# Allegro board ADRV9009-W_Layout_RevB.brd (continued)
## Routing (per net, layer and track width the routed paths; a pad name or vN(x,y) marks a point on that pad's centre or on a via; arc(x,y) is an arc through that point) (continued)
ORX2_UNBAL: length 2.3
  BOTTOM w0.203: C251.1 18.65,18
  BOTTOM w0.394: R223.2 17.76,17.01 C224.1 18.65,18
OUT1: length 3.9
  BOTTOM w0.203: 96.65,60.56 96.97,60.56 97.16,60.56 97.47,60.87 R420.1 ; 96.65,60.56 96.63,60.58 R418.1 ; 96.65,60.56 95.11,60.56 95.04,60.63 U401.64
OUT1_N: length 4
  BOTTOM w0.203: 96.65,60.2 96.63,60.18 R418.2 ; 96.65,60.2 95.11,60.2 95.04,60.13 U401.65 ; 96.65,60.2 97.13,60.2 97.47,59.86 R419.1
OUT3: length 3.9
  BOTTOM w0.203: 96.72,63.56 97.57,63.56 R424.1 ; 96.72,63.56 95.16,63.56 95.09,63.63 94.47,63.63 U401.58 ; 96.72,63.56 R423.2
OUT3_N: length 3.9
  BOTTOM w0.203: R425.1 97.57,63.2 96.72,63.2 ; 96.72,63.2 95.16,63.2 95.09,63.13 U401.59 ; 96.72,63.2 R423.1
OUT5: length 19.1
  TOP w0.203: C410.1 105.16,64.38 105.42,64.65 105.42,64.89 105.22,65.09 103.66,65.09 103.25,64.68 95.25,64.68 94.21,65.72 91.52,65.72 91.11,66.14 91.11,66.66 91,66.78 ; 91,66.78 R426.1 ; 91,66.78 90.93,66.84 v2(90.93,67.34)
  BOTTOM w0.203: U401.49 91.04,66.29 91.11,66.36 91.11,67.17 v2(90.93,67.34)
OUT5_N: length 19.1
  TOP w0.203: C411.1 106.05,64.38 105.78,64.65 105.78,65.03 105.37,65.44 103.51,65.44 103.11,65.04 95.4,65.04 94.36,66.08 91.67,66.08 91.47,66.28 91.47,66.66 91.63,66.83 ; 91.63,66.83 91.65,66.84 v2(91.65,67.34) ; 91.63,66.83 91.63,66.82 R426.2
  BOTTOM w0.203: U401.50 91.54,66.26 91.47,66.33 91.47,67.17 v2(91.65,67.34)
OUT7: length 13.9
  TOP w0.203: 87.95,66.83 88.11,66.66 88.11,66.28 87.91,66.08 85.92,66.08 85.35,66.65 80.13,66.65 79.82,66.97 78.91,66.97 78.5,66.56 78.5,66.21 C412.1 ; 87.95,66.83 87.93,66.84 v2(87.93,67.34) ; 87.95,66.83 R427.1
  BOTTOM w0.203: v2(87.93,67.34) 88.11,67.17 88.11,66.33 88.04,66.26 U401.43
OUT7_N: length 13.8
  TOP w0.203: 88.58,66.78 88.65,66.84 v2(88.65,67.34) ; 88.58,66.78 88.47,66.66 88.47,66.14 88.06,65.72 85.77,65.72 85.2,66.3 79.99,66.3 79.67,66.61 79.06,66.61 78.86,66.41 78.86,66.21 C413.1 ; 88.58,66.78 R427.2
  BOTTOM w0.203: U401.44 88.54,66.29 88.47,66.36 88.47,67.17 v2(88.65,67.34)
OUT8: length 22.7
  TOP w0.203: 85.73,67.76 R428.1 ; 85.73,67.76 70.86,67.76 70.58,67.48 70.18,67.48 69.9,67.76 69.49,67.76 68.75,67.01 68.75,66.61 68.87,66.49 69.45,66.49 69.59,66.35 69.59,66.06 R429.1 ; 85.73,67.76 86.57,67.76 86.79,67.53 86.79,67.16 86.66,67.04 86.66,66.95 86.55,66.84 v2(86.43,66.84)
  BOTTOM w0.203: v2(86.43,66.84) 86.61,66.66 86.61,66.33 86.54,66.26 U401.40
OUT8_N: length 22.7
  TOP w0.203: v2(87.15,66.84) 87.15,67.68 86.71,68.11 85.73,68.11 ; 85.73,68.11 69.34,68.11 68.39,67.16 R430.1 ; 85.73,68.11 R428.2
  BOTTOM w0.203: v2(87.15,66.84) 86.97,66.66 86.97,66.36 87.04,66.29 U401.41
OUT12: length 7.1
  BOTTOM w0.203: R431.2 80.57,63.56 ; 80.57,63.56 82.03,63.56 82.26,63.33 82.26,61.65 82.7,61.2 83.47,61.2 83.54,61.13 U401.28 ; 80.57,63.56 80.01,63.56 79.77,63.32 R432.1
OUT12_N: length 7.2
  BOTTOM w0.203: R433.1 79.76,64.21 80.05,63.92 80.58,63.92 ; 80.58,63.92 82.17,63.92 82.62,63.48 82.62,61.79 82.85,61.56 83.47,61.56 83.54,61.63 U401.29 ; 80.58,63.92 80.57,63.93 R431.1
OUT13: length 3.9
  BOTTOM w0.203: 81.75,59.71 81.06,59.71 R436.1 ; 81.75,59.71 R434.1 ; 81.75,59.71 83.63,59.71 83.72,59.63 U401.25
OUT13_N: length 3.9
  BOTTOM w0.203: R434.2 81.75,60.07 ; 81.75,60.07 83.62,60.07 83.68,60.13 U401.26 ; 81.75,60.07 81.06,60.07 R435.1
PWRSUPPLYENABLE: length 111.8
  TOP w0.305: R902.1 79.66,19.07 v2(79.68,19.06)
  L8_SIG w0.394: v1(140.3,60.87) 142.31,60.87 143.58,59.6 143.58,49.9 145.04,48.45 145.04,33.69 143.58,32.24 143.58,22.2 143.19,21.81 142.66,21.81 142.31,21.46 142.31,20.87 141.98,20.54 141.39,20.54 138.89,18.04 127.56,18.04 127.02,18.58 123.59,18.58 122.42,19.75 121.66,19.75 121.39,19.48 120.1,19.48 120.09,19.47 119.55,19.47 119.54,19.48 116.34,19.48 115.71,20.11 98.31,20.11 97.31,19.11 79.73,19.11 v2(79.68,19.06)
  BOTTOM w0.394: v1(140.3,60.87) 139.74,60.31 P801.D1
REF_CLK_IN+: length 62.9
  BOTTOM w0.203: 78.74,59.71 79.47,59.71 R436.2 ; 78.74,59.71 77.41,59.71 ; 78.74,59.71 C445.2 ; 77.41,59.71 L401.1 ; 77.41,59.71 77.09,59.71 arc(72.18,59.25) 67.44,57.88 arc(67.04,57.73) 66.63,57.6 66.64,57.6 arc(58.87,55.89) 50.94,55.27 50.94,55.27 arc(47.52,53.86) 46.11,50.44 46.11,45.64 arc(44.94,42.82) 42.12,41.65 38.29,41.65 arc(35.41,41.03) 33.1,39.2 arc(32.44,38) 32.21,36.64 32.21,35.86 ; 32.21,35.86 32.21,35.59 arc(32.24,35.42) C103.1 ; 32.21,35.86 R121.1
REF_CLK_IN-: length 63.5
  BOTTOM w0.203: R121.2 31.85,35.86 ; 31.85,35.86 31.85,35.59 arc(31.81,35.42) C104.1 ; 31.85,35.86 31.85,36.64 arc(32.1,38.12) 32.83,39.43 arc(35.26,41.35) 38.29,42 42.12,42 arc(44.69,43.07) 45.75,45.64 45.75,50.44 arc(47.27,54.11) 50.94,55.62 arc(58.82,56.24) 66.54,57.94 arc(66.93,58.06) 67.31,58.21 arc(72.11,59.6) 77.09,60.07 77.41,60.07 ; 77.41,60.07 L401.2 ; 77.41,60.07 78.74,60.07 ; 78.74,60.07 79.47,60.07 R435.2 ; 78.74,60.07 C445.1
RESETB: length 120
  TOP w0.254: U101.J4 v3(35.64,31.68)
  TOP w0.394: R804.1 129.42,48.5 128.99,48.07 TP803.1
  L5_SIG w0.114: v3(35.64,31.68) 36.08,31.23 38.14,31.23 38.44,31.53 38.44,31.81 38.74,32.11 39,32.11 39.22,32.34 39.22,33.91 39.23,33.92 39.23,34.74 38.44,35.52 38.44,39.08 38.65,39.28 39.89,39.28 40.83,40.22 v5(40.9,40.22) 48.34,40.22 51.1,37.46 68.6,37.46 72.43,41.29 72.43,41.85 73.08,42.5 73.51,42.5 74.93,43.92 76.2,43.92 78.35,46.07 88.39,46.07 88.74,46.43 101.89,46.43 107.63,52.17 113.92,52.17 114.81,51.28 120.46,51.28 123.68,48.07 TP803.1
  BOTTOM w0.305: v5(40.9,40.22) 40.9,39.35 40.16,38.61 R110.2
RF_EXT_LO+: length 5.8
  TOP w0.203: U101.B8 v3(29.24,34.88)
  L10_SIG w0.254: v5(25.19,34.37) 25.47,34.09 27.83,34.09 27.98,34.24 28.89,34.24 29.24,34.58 v3(29.24,34.88)
  BOTTOM w0.203: C304.2 v5(25.19,34.37)
RF_EXT_LO-: length 5.8
  TOP w0.203: U101.B7 v3(29.24,33.28)
  L10_SIG w0.254: v5(25.19,33.45) 25.47,33.73 27.97,33.73 28.13,33.89 28.96,33.89 29.24,33.61 v3(29.24,33.28)
  BOTTOM w0.203: C305.2 v5(25.19,33.45)
RF_SYNTH_VTUNE: length 29.9
  TOP w0.203: C136.1 56.46,41.45 P104.5
  TOP w0.254: v5(34.04,35.68) U101.G9
  L7_SIG w0.114: v5(34.04,35.68) 34.42,36.06 34.42,38.13 34.83,38.54 34.98,38.54 35.18,38.74 35.18,38.9 35.56,39.28 42.99,39.28 44.9,41.19 46.99,41.19 48.33,42.52 51.95,42.52 52.13,42.34 53.24,42.34 53.48,42.58 55.18,42.58 P104.5
RFO_1: length 1
  TOP w0.203: 35.49,51.45 35.5,51.8 ; 35.5,52.39 C337.1
  TOP w0.394: 35.5,51.8 35.5,52.39
RFO_2: length 1
  TOP w0.203: 34.18,16.7 34.18,16.35 ; 34.17,15.77 C336.1
  TOP w0.394: 34.18,16.35 34.17,15.77
RX1_BAL+: length 3.3
  TOP w0.127: 18.86,38.89 T201.5
  TOP w0.203: 20.46,39.24 19.85,39.24 arc(19.32,39.15) 18.86,38.89 arc(18.8,38.84) T201.5 ; 20.46,39.24 C204.1 ; 20.46,39.24 20.84,39.24 arc(21.2,39.17) R205.1
RX1_BAL-: length 3.1
  TOP w0.203: 20.46,39.6 19.84,39.6 arc(19.25,39.71) T201.4 ; 20.46,39.6 C204.2 ; 20.46,39.6 20.84,39.6 arc(21.2,39.67) R206.1
RX1_ENABLE: length 37
  TOP w0.254: U101.M5 v3(38.04,31.68)
  TOP w0.305: P104.7 53.91,41.44 R117.1
  L5_SIG w0.114: v3(38.04,31.68) 37.67,32.04 37.15,32.04 36.77,32.42 36.77,32.62 36.58,32.81 36.38,32.81 36.06,33.14 36.06,33.46 35.3,34.21 35.3,41.05 38.35,44.1 39.49,44.1 40.25,44.86 49.86,44.86 53.34,41.38 P104.7
  BOTTOM w0.203: R839.1 P104.7
RX1_IN+: length 8.4
  TOP w0.203: U101.A9 28.7,35.41 arc(28.58,35.49) 28.44,35.52 arc(27.72,35.68) 27.12,36.11 25.16,38.34 arc(24.28,39) 23.21,39.24 ; 23.21,39.24 23.2,39.24 C207.1 ; 23.21,39.24 arc(23.12,39.24) 23.02,39.24 arc(22.56,39.17) R205.2
RX1_IN-: length 8.4
  TOP w0.203: 23.22,39.6 23.2,39.6 C207.2 ; 23.22,39.6 arc(24.43,39.32) 25.42,38.58 27.39,36.35 arc(27.86,36) 28.44,35.88 28.5,35.88 arc(28.63,35.9) 28.74,35.98 U101.A10 ; 23.22,39.6 arc(23.11,39.6) 23.01,39.6 arc(22.55,39.66) R206.2
RX1_UNBAL: length 2.2
  TOP w0.203: C248.1 13.11,40.1
  TOP w0.394: R202.2 C203.1 12.51,40.61 arc(12.65,40.48) 12.79,40.34 arc(12.95,40.22) 13.11,40.1
RX2_BAL+: length 3.6
  TOP w0.127: T202.5 19.12,29.57
  TOP w0.203: 20.46,29.75 20.84,29.75 arc(21.2,29.67) R212.1 ; 20.46,29.75 19.85,29.75 arc(19.47,29.7) 19.12,29.57 arc(18.92,29.44) T202.5 ; 20.46,29.75 C211.1
RX2_BAL-: length 3.1
  TOP w0.203: 20.46,30.1 19.84,30.1 arc(19.25,30.22) T202.4 ; 20.46,30.1 C211.2 ; 20.46,30.1 20.84,30.1 arc(21.2,30.17) R213.1
RX2_ENABLE: length 31.3
  TOP w0.254: U101.M7 v3(38.04,34.08)
  TOP w0.305: P104.8 53.91,38.77 R116.1
  L5_SIG w0.114: v3(38.04,34.08) 37.66,34.46 37.66,35 37.37,35.29 37.08,35.29 36.84,35.53 36.84,40.69 38.6,42.45 43.05,42.45 43.44,42.85 48.19,42.85 50.93,40.11 52.58,40.11 P104.8
  BOTTOM w0.203: R842.1 P104.8
RX2_IN+: length 7.6
  TOP w0.203: 23.21,29.74 23.02,29.75 arc(22.56,29.69) R212.2 ; 23.21,29.74 C214.1 ; 23.21,29.74 arc(23.98,29.85) 24.7,30.16 arc(25.8,30.85) 26.84,31.61 arc(27.61,32.06) 28.47,32.28 arc(28.69,32.23) U101.A5
RX2_IN-: length 7.7
  TOP w0.203: U101.A6 28.7,32.74 arc(28.58,32.66) 28.44,32.63 arc(27.47,32.39) 26.62,31.89 arc(25.59,31.14) 24.52,30.47 arc(23.88,30.19) 23.19,30.1 ; 23.19,30.1 23.02,30.1 arc(22.56,30.17) R213.2 ; 23.19,30.1 arc(23.2,30.17) C214.2
RX2_UNBAL: length 4.1
  TOP w0.203: C249.1 12.96,30.56
  TOP w0.394: 12.96,30.56 11.88,30.56 arc(11.1,30.23) 10.78,29.45 C210.1 R209.2
SERDIN0+: length 3
  BOTTOM w0.203: P801.A22 143.55,33.02 arc(143.61,32.88) 143.75,32.82 145.7,32.82 arc(145.87,32.85) 146.02,32.95 C113.1
SERDIN0-: length 3
  BOTTOM w0.203: C114.1 146.02,32.33 arc(145.87,32.43) 145.7,32.46 143.75,32.46 arc(143.61,32.4) 143.55,32.26 P801.A23
SERDIN1+: length 3
  BOTTOM w0.203: C115.1 146.02,22.79 arc(145.87,22.69) 145.7,22.66 143.75,22.66 arc(143.61,22.72) 143.55,22.86 P801.A30
SERDIN1-: length 3
  BOTTOM w0.203: C116.1 146.02,22.17 arc(145.87,22.27) 145.7,22.3 143.75,22.3 arc(143.61,22.24) 143.55,22.1 P801.A31
SERDIN2+: length 1.4
  TOP w0.203: v1(141.64,58.04) C117.1
  BOTTOM w0.203: P801.C2 v1(141.64,58.04)
SERDIN2-: length 1.7
  TOP w0.203: v1(141.64,56.77) C118.1
  BOTTOM w0.203: 141.19,57.22 v1(141.64,56.77) ; 141.19,57.22 P801.C3 141.03,57.4 141.19,57.24 141.19,57.22
SERDIN3+: length 3
  BOTTOM w0.203: P801.A26 143.55,27.94 arc(143.61,27.8) 143.75,27.74 145.7,27.74 arc(145.87,27.77) 146.02,27.87 C119.1
SERDIN3-: length 3
  BOTTOM w0.203: C120.1 146.02,27.25 arc(145.87,27.35) 145.7,27.38 143.75,27.38 arc(143.61,27.32) 143.55,27.18 P801.A27
SERDOUT0+: length 3
  BOTTOM w0.203: P801.A2 143.55,58.42 arc(143.61,58.28) 143.75,58.22 145.7,58.22 arc(145.87,58.25) 146.02,58.35 C105.1
SERDOUT0-: length 3
  BOTTOM w0.203: C106.1 146.02,57.73 arc(145.87,57.83) 145.7,57.86 143.75,57.86 arc(143.61,57.8) 143.55,57.66 P801.A3
SERDOUT1+: length 3
  BOTTOM w0.203: C107.1 146.02,53.27 arc(145.87,53.17) 145.7,53.14 143.75,53.14 arc(143.61,53.2) 143.55,53.34 P801.A6
SERDOUT1-: length 3
  BOTTOM w0.203: C108.1 146.02,52.65 arc(145.87,52.75) 145.7,52.78 143.75,52.78 arc(143.61,52.72) 143.55,52.58 P801.A7
SERDOUT2+: length 1.4
  TOP w0.203: C109.1 141.67,52.93 v1(141.67,52.95)
  BOTTOM w0.203: v1(141.67,52.95) 141.66,52.95 P801.C6
SERDOUT2-: length 1.4
  TOP w0.203: v1(141.64,51.69) C110.1
  BOTTOM w0.203: v1(141.64,51.69) P801.C7
SERDOUT3+: length 3
  BOTTOM w0.203: C111.1 146.02,48.19 arc(145.87,48.09) 145.7,48.06 143.75,48.06 arc(143.61,48.12) 143.55,48.26 P801.A10
SERDOUT3-: length 3
  BOTTOM w0.203: C112.1 146.02,47.57 arc(145.87,47.67) 145.7,47.7 143.75,47.7 arc(143.61,47.64) 143.55,47.5 P801.A11
SPI_CLK: length 112.9
  TOP w0.254: U101.K9 v3(36.44,35.68) ; U403.3 120.14,47.94 121.68,46.4 121.68,44.26 TP805.1
  TOP w0.305: TP805.1 121.6,41.95 129.64,41.95 131.17,43.47 R806.1
  L7_SIG w0.114: TP805.1 119.37,41.95 105.16,41.95 100.9,46.2 89.79,46.2 v4(89.47,45.89)
  L8_SIG w0.114: v4(89.47,45.89) 89.29,46.07 77.72,46.07 77.09,45.44 72.39,45.44 70.36,43.41 51.69,43.41 45.21,36.93 43.18,36.93 41.54,35.29 37.08,35.29 36.69,35.68 v3(36.44,35.68)
SPI_CLK_9528: length 43.5
  TOP w0.203: U403.12 v2(120.14,53.63)
  L7_SIG w0.114: v2(120.14,53.63) 98.81,53.63 98.43,54.01 87.82,54.01 83.76,58.08 82.42,58.08 v2(82.21,58.29)
  BOTTOM w0.254: v2(82.21,58.29) 82.46,58.04 83.38,58.04 83.47,58.13 U401.22
SPI_CS0: length 119.8
  TOP w0.254: v1(139.1,42.87) 138.89,42.87 138.55,42.53 R832.2 R846.1 ; U402.7 116.71,47.86 117.33,47.24 118.65,47.24 119.9,45.99 TP816.1 ; U101.K10 v3(36.44,36.48)
  L7_SIG w0.114: TP816.1 119.34,44.84 116.88,44.84 115,42.97 105.67,42.97 101.6,47.03 96.52,47.03 96.01,47.54 v4(88.2,47.54)
  L8_SIG w0.114: v4(88.2,47.54) 72.08,47.54 68.84,44.3 48.96,44.3 44.88,40.22 43.42,40.22 40.43,37.22 40.36,37.22 40.01,36.88 36.84,36.88 v3(36.44,36.48)
  L8_SIG w0.254: TP816.1 121.98,44.49 123.63,44.49 124.64,43.48 138.49,43.48 v1(139.1,42.87)
SPI_CS1: length 34.8
  TOP w0.254: 121.44,50.48 U403.5
  TOP w0.305: U402.1 120.6,51.32 121.44,50.48 122.03,51.08 123.99,51.08 TP815.1 130.59,49.7 130.74,49.86 134.53,49.86 135.89,48.49 135.89,47.6 136.27,47.22 136.74,47.22 137.12,46.84 137.12,40.05 137.5,39.67 138.21,39.67 138.55,40.01 R833.2 R847.1
SPI_CS_9528: length 46.6
  TOP w0.203: U403.10 v2(121.44,53.63)
  L7_SIG w0.114: v2(81.7,57.55) 83.33,57.55 87.31,53.58 87.4,53.58 87.6,53.38 98.05,53.38 98.68,52.74 103.63,52.74 104.14,52.24 105.03,52.24 105.54,52.74 114.81,52.74 115.06,53 120.8,53 v2(121.44,53.63)
  BOTTOM w0.254: U401.21 83.78,57.63 83.69,57.63 83.62,57.55 v2(81.7,57.55)
SPI_DIN: length 114.2
  TOP w0.254: U403.4 120.79,48.18 123,45.96 TP806.1 ; U101.J9 v3(35.64,35.68)
  TOP w0.305: TP806.1 125.39,43.98 129.45,43.98 130.14,44.67 R807.1
  L7_SIG w0.114: TP806.1 122.03,47.33 117.4,47.33 113.93,43.86 106.18,43.86 102.24,47.8 96.97,47.8 96.58,48.19 85.49,48.19 v3(84.01,46.71)
  L8_SIG w0.114: v3(35.64,35.68) 36.03,36.06 40.43,36.06 40.85,36.48 41.33,36.48 43.06,38.2 44.33,38.2 49.98,43.85 69.6,43.85 72.45,46.7 84,46.7 v3(84.01,46.71)
SPI_DIN_9528: length 42.5
  TOP w0.203: U403.11 v2(120.79,56.55)
  L7_SIG w0.114: v2(120.79,56.55) 119.01,54.78 109.35,54.78 109.1,55.03 94.62,55.03 93.72,55.93 87.88,55.93 85.09,58.71 83.36,58.71 v2(83.28,58.63)
  BOTTOM w0.254: v2(83.28,58.63) 83.68,58.63 U401.23
SPI_DOUT: length 31.1
  TOP w0.203: 116.2,48.63 U402.6 ; 117.59,45.99 TP811.1
  TOP w0.254: U402.3 116.21,48.65 116.19,48.62 116.19,47.39 118.66,44.92 118.66,42.26 119.6,41.31 132.84,41.31 133.69,42.16 134.13,42.16 134.53,42.56 134.53,42.81 135.26,43.54 135.51,43.54 136.06,44.09 136.06,45.94 R845.1
SPI_DOUT_9528: length 38.8
  TOP w0.203: R453.2 114.11,55.92 TP400.1
  L7_SIG w0.114: TP400.1 96.78,55.92 93.73,58.97 86.49,58.97 86.06,59.4 83.01,59.4 v2(82.56,58.95)
  BOTTOM w0.254: v2(82.56,58.95) 82.83,59.21 83.59,59.21 83.67,59.13 83.81,59.13 U401.24
SPI_DOUT_DUT: length 91.5
  TOP w0.254: R454.2 116.07,44.56 TP401.1 ; U101.J10 v3(35.64,36.48)
  L7_SIG w0.097: 39.49,33.69 39.89,33.69
  L7_SIG w0.114: 39.49,33.69 37.95,33.69 37.63,34.01 37.63,34.24 37.4,34.46 37.1,34.46 36.07,35.5 36.07,36.04 v3(35.64,36.48) ; v2(79.64,37.38) 78.43,37.38 77.03,35.98 77.03,35.84 74.6,33.41 45.85,33.41 45.3,33.96 44.71,33.96 44.45,34.22 43.2,34.22 42.67,33.69 39.89,33.69
  BOTTOM w0.394: v2(79.64,37.38) 111.83,37.38 TP401.1
STATUS_0: length 3.2
  TOP w0.203: R444.1 v2(95.57,65.95)
  BOTTOM w0.254: R444.1 95.57,66.59 ; v2(95.57,65.95) 94.75,65.13 U401.55
  BOTTOM w0.394: 95.57,66.59 v2(95.57,65.95)
STATUS_1: length 4.5
  TOP w0.203: v2(96.64,65.95) 96.64,66.69 R445.1
  BOTTOM w0.254: v2(96.64,65.95) 96.52,65.95 95.2,64.63 U401.56
  BOTTOM w0.394: v2(96.64,65.95) R443.1
SYNCINB0+: length 148.6
  TOP w0.203: R820.1 137.81,49.13 v1(137.83,49.15)
  TOP w0.254: U101.M4 v3(38.04,30.88)
  L7_SIG w0.091: v3(38.04,30.88) 38.04,30.55 37.71,30.21 37.71,29.15 37.93,28.92 39.84,28.92 40.77,27.98 44.57,27.98 44.96,27.6 46.23,27.6 49.14,24.68 59.68,24.68 60.57,25.57 105.19,25.57 110.14,20.62 111.79,20.62 113.19,19.22 116.24,19.22 119.66,15.79 126.63,15.79 127.14,16.3 ; 127.14,16.3 127.77,16.94 132.45,16.94 136.77,21.26 137.78,21.26 139.91,23.39 139.91,26.5 141.36,27.95 141.97,27.95 143.75,29.73 143.75,48.07 143.14,48.69 138.29,48.69 v1(137.83,49.15) ; 127.14,16.3 TP809.1
SYNCINB0-: length 147.4
  TOP w0.203: R821.1 137.81,47.86 v1(137.83,47.88)
  TOP w0.254: U101.M3 v3(38.04,30.08)
  L7_SIG w0.091: TP810.1 126.96,16.48 ; 126.96,16.48 126.96,16.48 126.52,16.05 119.77,16.05 116.34,19.48 113.29,19.48 111.9,20.87 110.25,20.87 105.29,25.83 60.46,25.83 59.57,24.94 49.25,24.94 46.34,27.85 45.07,27.85 44.68,28.24 40.87,28.24 40.09,29.02 40.09,29.3 39.76,29.62 38.14,29.62 38.04,29.72 v3(38.04,30.08) ; 126.96,16.48 127.67,17.19 132.34,17.19 136.66,21.51 137.68,21.51 139.66,23.49 139.66,26.61 141.26,28.21 141.87,28.21 143.5,29.84 143.5,47.97 143.03,48.44 138.19,48.44 137.93,48.69 137.8,48.69 137.42,48.31 137.42,48 137.55,47.88 137.83,47.88 v1(137.83,47.88)
SYNCINB1+: length 107.9
  TOP w0.203: R828.1 134.46,26.73 v1(134.02,26.29)
  TOP w0.254: U101.L4 v3(37.24,30.88)
  L7_SIG w0.091: 116.02,21.44 115.71,21.13 114.54,21.13 113.4,22.27 111.01,22.27 109.02,24.26 108.88,24.26 105.28,27.86 49.54,27.86 48.4,29 46.08,29 44.05,31.03 40.01,31.03 39.77,31.28 38.62,31.28 38.36,31.54 38.36,31.81 38.17,32 37.9,32 37.66,31.76 37.66,31.33 37.33,30.99 37.33,30.96 v3(37.24,30.88) ; 116.02,21.44 116.66,22.08 119.06,24.49 120.63,24.49 121.39,23.73 122.87,23.73 123.26,24.11 124.38,24.11 125.01,23.47 127.38,23.47 128.4,24.49 131.89,24.49 133.19,25.78 133.93,25.78 134.02,25.87 v1(134.02,26.29) ; 116.02,21.44 116.02,21.58 TP812.1
SYNCINB1-: length 107.8
  TOP w0.203: R829.1 134.47,25.47 v1(134.02,25.02)
  TOP w0.254: U101.L3 v3(37.24,30.08)
  L7_SIG w0.091: v1(134.02,25.02) 134.02,25.28 133.77,25.53 133.29,25.53 132,24.23 128.5,24.23 127.49,23.22 124.91,23.22 124.27,23.85 123.36,23.85 122.98,23.47 121.29,23.47 120.52,24.23 119.17,24.23 116.84,21.9 ; v3(37.24,30.08) 37.24,30.42 37.56,30.74 37.56,30.74 37.58,30.76 37.58,30.89 37.89,31.2 38.17,31.2 38.36,31.01 38.36,30.89 38.73,30.53 39.76,30.53 40.01,30.78 43.95,30.78 45.98,28.75 48.29,28.75 49.43,27.61 105.18,27.61 108.78,24 108.92,24 110.9,22.02 113.29,22.02 114.44,20.87 115.81,20.87 116.84,21.9 ; TP813.1 117.55,21.19 116.84,21.9
SYNCOUTB0+: length 104.8
  TOP w0.203: TP801.1 128.63,52.83 R802.1 ; U101.M14 v3(37.24,38.88)
  L8_SIG w0.091: v3(37.24,38.88) 37.31,38.88 37.54,39.1 37.54,39.35 37.78,39.59 38.42,39.59 38.72,39.29 39.88,39.29 40.19,38.98 40.87,38.98 42.42,40.53 42.42,40.81 46.29,44.68 47.69,44.68 49.21,46.2 69.22,46.2 71.64,48.62 71.64,53.51 72.09,53.96 100.38,53.96 100.59,53.76 117.99,53.76 118.87,54.65 123.83,54.65 126.03,52.45 127.71,52.45 127.8,52.54 TP801.1
SYNCOUTB0-: length 104.7
  TOP w0.203: U101.M13 v3(38.04,38.88) ; R803.1 128.65,51.84 TP802.1
  L8_SIG w0.091: TP802.1 127.8,52.11 127.71,52.2 125.92,52.2 123.72,54.4 118.98,54.4 118.09,53.51 100.48,53.51 100.28,53.71 72.19,53.71 71.89,53.41 71.89,48.52 69.32,45.95 49.32,45.95 47.8,44.43 46.4,44.43 42.67,40.7 42.67,40.43 40.98,38.73 40.14,38.73 39.99,38.58 39,38.58 38.97,38.55 38.7,38.55 38.68,38.58 38.67,38.58 38.46,38.78 38.46,39.18 38.32,39.33 37.89,39.33 37.8,39.24 37.8,39.04 37.96,38.88 v3(38.04,38.88)
SYNCOUTB1+: length 178.6
  TOP w0.203: R814.1 133.97,24.42 133.48,23.93 130.54,23.93 128.97,25.5 126.95,25.5 126.64,25.81 126.3,25.94 126.19,26.21 TP807.1
  TOP w0.254: U101.L14 v5(37.24,39.68)
  L8_SIG w0.091: TP807.1 126.13,26.06 126.18,25.94 126.3,25.89 126.61,25.89 127.94,24.57 140.56,24.57 140.94,24.94 140.94,25.31 141.35,25.73 141.59,25.73 142.13,26.26 142.13,33.23 143.43,34.53 143.43,48 141.83,49.6 141.76,49.65 141.75,49.66 141.73,49.67 133.51,49.67 131.45,51.73 131.45,52.64 126.39,57.7 110.47,57.7 107.8,55.03 95.02,55.03 94.51,55.54 82.45,55.54 82.32,55.67 70.72,55.67 70.23,55.18 70.23,53.87 70.49,53.61 70.49,48.93 68.33,46.78 48.58,46.78 47.88,46.08 46.29,46.08 44.61,44.39 40.29,44.39 36.07,40.17 36.07,39.58 36.45,39.2 36.74,39.2 36.83,39.29 36.83,39.95 36.92,40.04 37.15,40.04 37.24,39.95 v5(37.24,39.68)
SYNCOUTB1-: length 178.7
  TOP w0.203: TP808.1 125.91,25.5 126.17,25.61 126.44,25.51 126.8,25.15 128.82,25.15 130.39,23.58 133.48,23.58 133.97,23.09 R815.1
  TOP w0.254: U101.L13 v5(36.44,38.88)
  L8_SIG w0.091: v5(36.44,38.88) 36.36,38.96 36.34,38.96 35.82,39.48 35.82,40.28 40.18,44.65 44.5,44.65 46.19,46.33 47.78,46.33 48.47,47.03 68.22,47.03 70.23,49.04 70.23,53.51 69.98,53.76 69.98,55.28 70.61,55.92 82.43,55.92 82.55,55.79 94.62,55.79 95.13,55.28 107.7,55.28 110.37,57.95 126.49,57.95 131.7,52.74 131.7,51.83 133.61,49.92 141.81,49.92 141.9,49.86 141.91,49.86 141.92,49.86 141.94,49.86 141.98,49.81 141.98,49.81 142.32,49.47 143.68,48.11 143.68,34.43 142.38,33.13 142.38,26.15 141.7,25.47 141.46,25.47 141.19,25.21 141.19,24.84 140.67,24.31 127.83,24.31 126.51,25.64 126.25,25.64 126.09,25.7 125.97,25.65 TP808.1
SYSREF_CLK_IN+: length 2.4
  BOTTOM w0.203: U401.70 95.04,57.63 95.11,57.56 96.2,57.56 R451.2
SYSREF_CLK_IN-: length 2.4
  BOTTOM w0.203: R452.2 96.15,57.19 96.03,57.19 96.02,57.2 95.11,57.2 95.04,57.13 U401.71
SYSREF_IN+: length 89.9
  TOP w0.254: U101.K3 v3(36.44,30.08)
  L7_SIG w0.091: v2(73.88,63.33) 74.08,63.54 76.46,63.54 77.98,62.02 77.98,61 80.27,58.71 80.27,55.92 82.25,53.93 82.25,49.24 80.4,47.39 67.05,47.39 64.28,44.62 46.12,44.62 43.84,42.33 36.47,42.33 32.66,38.52 32.66,37.63 31.86,36.83 31.86,36.02 32.51,35.37 32.51,34.58 32.91,34.19 32.91,33.94 33.1,33.75 33.35,33.75 34.51,32.59 34.51,31.52 34.75,31.28 34.95,31.28 35.65,30.58 36.01,30.58 36.44,30.15 v3(36.44,30.08)
  BOTTOM w0.203: v2(73.88,63.33) 74.1,63.56 77.64,63.56 77.89,63.32 R432.2
SYSREF_IN-: length 89.8
  TOP w0.254: U101.K4 v3(36.44,30.88)
  L7_SIG w0.091: v2(73.88,64.15) 74.23,63.79 76.56,63.79 78.23,62.12 78.23,61.11 80.52,58.82 80.52,56.03 82.51,54.04 82.51,49.14 80.5,47.13 67.15,47.13 64.38,44.36 46.23,44.36 43.94,42.08 36.58,42.08 32.91,38.41 32.91,37.52 32.11,36.72 32.11,36.13 32.77,35.47 32.77,34.69 33.06,34.4 33.37,34.4 33.56,34.21 33.56,33.89 34.66,32.8 34.67,32.8 34.97,32.8 35.16,32.61 35.16,31.43 35.76,30.83 36.39,30.83 v3(36.44,30.88)
  BOTTOM w0.203: v2(73.88,64.15) 74.1,63.92 77.6,63.92 77.89,64.21 R433.2
TEST: length 176.3
  TOP w0.203: 140.98,38.46 137.79,38.46 135.38,40.87 R836.1
  TOP w0.254: U101.J6 v3(35.64,33.28)
  TOP w0.394: R112.1 R111.2 143.55,11.65 144.95,13.05 144.95,20.46 143.61,21.8 143.61,28.09 142.12,29.57 142.12,30.63 140.98,31.78 140.98,38.46 142.34,39.82 142.34,44.65 v1(141.67,45.32)
  L7_SIG w0.114: v3(35.64,33.28) 35.97,32.94 37.47,32.94 37.73,33.19 38.44,33.19 38.7,32.94 44.7,32.94 45.84,31.8 51.55,31.8 51.68,31.93 53.22,31.93 53.85,31.3 76.11,31.3 78.97,34.16 78.97,35.45 80.27,36.74 80.27,37.95 79.95,38.27 79.95,39.35 80.71,40.11 81.54,40.11 82.49,41.06 82.49,42.01 85.6,45.12 91.06,45.12 91.39,45.46 100.26,45.46 104.4,41.31 121.67,41.31 122.62,42.27 TP817.1 124.46,44.11 126.8,46.45 133.31,46.45 133.67,46.09 140.9,46.09 v1(141.67,45.32)
TX1_ENABLE: length 31.9
  TOP w0.254: U101.M6 v3(38.04,32.48)
  TOP w0.305: R115.1 51.25,41.44 P104.9
  L5_SIG w0.114: v3(38.04,32.48) 37.7,32.81 37.22,32.81 36.83,33.21 36.83,34.33 36.1,35.06 36.1,40.84 38.74,43.48 40.01,43.48 40.46,43.93 43.58,43.93 44.06,44.4 44.48,44.4 44.74,44.15 48.54,44.15 P104.9
  BOTTOM w0.203: R838.1 P104.9
TX2_ENABLE: length 24.7
  TOP w0.254: U101.M8 v3(38.04,34.88)
  TOP w0.305: P104.10 51.37,38.77 R114.1
  L5_SIG w0.114: v3(38.04,34.88) 38.04,35.2 37.63,35.61 37.63,35.84 37.63,35.84 37.63,39 38.67,40.04 40.09,40.04 41.68,41.63 48.51,41.63 P104.10
  BOTTOM w0.203: R841.1 P104.10
UNNAMED_2_ADRV9009_I127_RBIAS: length 2.5
  TOP w0.203: U101.C14 28.89,40.82 R101.1
UNNAMED_2_ADRV9009_I127_VDDA1_1: length 1.2
  TOP w0.254: v1(38.04,28.48) U101.M1
  BOTTOM w0.305: 37.96,28.55 v1(38.04,28.48)
  BOTTOM w0.394: C101.1 37.66,28.86 37.96,28.55
UNNAMED_2_ADRV9009_I127_VDDA1_2: length 0.9
  TOP w0.254: v1(30.04,33.28) U101.C7
  BOTTOM w0.203: v1(30.04,33.28) 30.06,33.25 C102.1
UNNAMED_2_ADRV9009_I127_VDDA1P1: length 1.7
  TOP w0.203: v5(30.08,36.48) 30.84,36.48
  TOP w0.254: 30.84,36.48 U101.D10
  BOTTOM w0.305: 30.1,36.87 30.1,36.84 30.08,36.82 v5(30.08,36.48)
  BOTTOM w0.394: C137.1 30.1,36.87
UNNAMED_2_CAP_I88_N2: length 1.2
  TOP w0.203: U101.E7 v5(32.44,34.08)
  BOTTOM w0.203: C103.2 32.34,34.3 arc(32.37,34.18) v5(32.44,34.08)
UNNAMED_2_CAP_I89_N2: length 1.2
  TOP w0.203: U101.E8 v5(31.64,34.08)
  BOTTOM w0.203: C104.2 31.71,34.25 arc(31.69,34.16) v5(31.64,34.08)
UNNAMED_2_CAP_I91_N2: length 123.6
  TOP w0.203: U101.P7 v3(39.56,33.35)
  L10_SIG w0.091: v3(39.56,33.35) arc(39.77,33.15) 40.05,33.08 40.28,33.08 arc(45.35,33.13) 50.42,33.29 arc(52.96,33.34) 55.5,33.3 111.63,33.3 arc(116.05,33.93) 120.11,35.77 arc(126.65,38.75) 133.77,39.77 135.45,39.77 arc(136.63,40.26) 137.12,41.45 137.12,50.66 arc(137.21,51.08) 137.45,51.44 139.3,53.29 arc(139.75,53.59) 140.27,53.7 arc(140.79,53.8) 141.23,54.09 142.2,55.07 arc(142.65,55.58) 143.02,56.15 arc(143.03,56.16) 143.04,56.17 arc(144.61,57.64) 146.7,58.15 146.98,58.15 arc(147.19,58.23) 147.32,58.42
  BOTTOM w0.203: C105.2 147.32,58.42
UNNAMED_2_CAP_I92_N2: length 123.6
  TOP w0.203: U101.P6 v3(39.56,32.55)
  L10_SIG w0.091: v3(39.56,32.55) arc(39.77,32.75) 40.05,32.83 40.28,32.83 arc(45.36,32.88) 50.43,33.03 arc(52.96,33.09) 55.49,33.05 111.63,33.05 arc(116.12,33.69) 120.25,35.56 arc(126.72,38.5) 133.77,39.52 135.45,39.52 arc(136.81,40.08) 137.38,41.45 137.38,50.66 arc(137.44,50.98) 137.63,51.26 138.87,52.5 139.48,53.11 arc(139.84,53.36) 140.27,53.44 arc(140.89,53.57) 141.41,53.91 141.84,54.35 142.44,54.95 142.44,54.95 arc(142.87,55.46) 143.24,56.02 arc(143.25,56.03) 143.25,56.04 arc(144.73,57.42) 146.69,57.9 146.98,57.9 146.99,57.9 arc(147.2,57.84) 147.32,57.66
  BOTTOM w0.203: C106.2 147.32,57.66
UNNAMED_2_CAP_I93_N2: length 126.7
  TOP w0.203: U101.P4 v3(39.56,30.95)
  L10_SIG w0.091: v3(39.56,30.95) arc(39.75,31.08) 39.98,31.13 41.05,31.13 arc(47.34,30.36) 53.25,28.11 arc(58.18,26.22) 63.41,25.57 111.63,25.57 arc(120.75,27.38) 128.49,32.55 arc(130.72,34.01) 133.35,34.46 137.92,34.46 arc(138.81,34.6) 139.6,35.02 arc(140.48,35.47) 141.47,35.6 141.48,35.6 arc(143.15,36.29) 143.84,37.96 143.84,46.44 arc(144.51,49.79) 146.42,52.61 146.48,52.68 arc(146.7,52.82) 146.95,52.87 146.96,52.87 arc(147.2,52.79) 147.32,52.58
  BOTTOM w0.203: C108.2 147.32,52.58
UNNAMED_2_CAP_I94_N2: length 126.7
  TOP w0.203: U101.P5 v3(39.7,31.62)
  L10_SIG w0.091: v3(39.7,31.62) 39.8,31.53 arc(39.96,31.42) 40.15,31.38 41.05,31.38 arc(47.4,30.61) 53.37,28.33 arc(58.24,26.47) 63.41,25.82 111.63,25.82 arc(120.66,27.62) 128.31,32.73 arc(130.63,34.25) 133.36,34.71 137.92,34.71 arc(138.73,34.84) 139.45,35.22 arc(140.41,35.71) 141.48,35.85 arc(142.97,36.47) 143.59,37.96 143.59,46.44 arc(144.28,49.89) 146.24,52.79 146.3,52.85 arc(146.6,53.05) 146.95,53.12 arc(147.16,53.19) 147.32,53.34
  BOTTOM w0.203: C107.2 147.32,53.34
UNNAMED_2_CAP_I95_N2: length 127.4
  TOP w0.254: v3(38.84,30.08) U101.N3
  L10_SIG w0.091: 147.32,47.5 arc(147.24,47.71) 147.02,47.77 arc(145.69,47.01) 145.16,45.57 145.16,34 arc(144.54,32.49) 143.03,31.86 133.56,31.86 arc(130.75,31.39) 128.3,29.94 arc(120.53,25.31) 111.63,23.7 61.58,23.7 arc(55.22,24.63) 49.49,27.55 arc(45.45,29.63) 40.95,30.35 39.36,30.35 arc(39.06,30.28) v3(38.84,30.08)
  BOTTOM w0.203: C112.2 147.32,47.5
UNNAMED_2_CAP_I96_N2: length 119.9
  TOP w0.203: C109.2 v3(142.91,51.69)
  TOP w0.254: v3(38.84,32.48) U101.N6
  L10_SIG w0.091: v3(38.84,32.48) arc(38.84,32.29) 39,32.2 41.89,32.2 arc(47.07,31.88) 52.16,30.92 arc(57.67,29.89) 63.26,29.56 111.63,29.56 arc(117.94,30.61) 123.57,33.64 arc(128.49,36.29) 134,37.21 136.94,37.21 arc(138.78,37.51) 140.42,38.37 arc(141.69,39.88) 142.15,41.8 142.15,48.76 arc(142.11,49.17) 141.98,49.56 141.77,50.03 arc(141.7,50.27) 141.68,50.52 arc(141.92,51.07) 142.49,51.26 arc(142.81,51.37) v3(142.91,51.69)
UNNAMED_2_CAP_I97_N2: length 119.9
  TOP w0.203: C110.2 v3(142.91,50.42)
  TOP w0.254: v3(38.84,31.68) U101.N5
  L10_SIG w0.091: v3(38.84,31.68) arc(39.01,31.87) 39.25,31.95 41.89,31.95 arc(47.03,31.63) 52.1,30.68 arc(57.63,29.64) 63.26,29.31 111.63,29.31 arc(118.02,30.37) 123.73,33.44 arc(128.57,36.05) 134,36.95 136.95,36.95 arc(138.86,37.27) 140.58,38.16 arc(141.92,39.76) 142.4,41.8 142.4,48.76 arc(142.36,49.22) 142.21,49.66 142.01,50.13 arc(141.95,50.32) 141.93,50.52 arc(142.09,50.88) 142.47,51.01 arc(142.82,50.81) v3(142.91,50.42)
UNNAMED_2_CAP_I98_N2: length 127.4
  TOP w0.254: v3(38.84,30.88) U101.N4
  L10_SIG w0.091: 147.32,48.26 arc(147.17,48.1) 146.97,48.02 arc(145.49,47.17) 144.91,45.57 144.91,34 arc(144.36,32.67) 143.03,32.12 133.57,32.12 arc(130.67,31.63) 128.13,30.14 arc(120.44,25.55) 111.63,23.95 61.58,23.95 arc(55.3,24.87) 49.64,27.75 arc(45.52,29.87) 40.95,30.6 39.05,30.6 arc(38.88,30.69) v3(38.84,30.88)
  BOTTOM w0.203: C111.2 147.32,48.26
UNNAMED_2_CAP_I99_N2: length 114.3
  TOP w0.203: v3(38.84,38.08) U101.N12
  L5_SIG w0.091: v3(38.84,38.08) arc(39.01,38.27) 39.26,38.35 40.83,38.35 arc(44.23,37.97) 47.45,36.82 arc(51.38,35.4) 55.54,34.92 110.04,34.92 arc(117.21,33.89) 123.81,30.9 arc(127.09,29.03) 130.53,27.49 arc(132.32,26.98) 134.18,26.81 138.19,26.81 arc(140.95,27.44) 143.17,29.2 144.96,31.44 145.4,31.98 arc(145.89,32.36) 146.49,32.49 146.86,32.49 147,32.49 arc(147.2,32.43) 147.32,32.26
  BOTTOM w0.203: C114.2 147.32,32.26
UNNAMED_2_CAP_I100_N2: length 114.3
  TOP w0.203: v3(38.84,38.88) U101.N13
  L5_SIG w0.091: v3(38.84,38.88) arc(39.01,38.68) 39.26,38.6 40.83,38.6 arc(44.29,38.22) 47.56,37.05 arc(51.44,35.64) 55.54,35.17 110.04,35.17 arc(117.28,34.13) 123.95,31.11 arc(127.2,29.26) 130.62,27.72 arc(132.37,27.23) 134.18,27.06 138.19,27.06 arc(140.84,27.67) 142.97,29.36 144.77,31.6 145.2,32.14 arc(145.78,32.59) 146.49,32.75 146.87,32.75 arc(147.13,32.82) 147.32,33.02
  BOTTOM w0.203: C113.2 147.32,33.02
UNNAMED_2_CAP_I101_N2: length 115.5
  TOP w0.203: v3(38.84,36.48) U101.N10
  L5_SIG w0.091: 147.32,22.1 arc(147.19,22.28) 146.98,22.35 146.51,22.35 arc(145.9,22.26) 145.37,21.94 arc(144.56,21.18) 143.82,20.35 arc(142.74,19.49) 141.39,19.19 133.34,19.19 arc(131.1,19.39) 128.93,19.99 arc(124.24,22.06) 119.79,24.59 arc(115.12,26.71) 110.04,27.44 60.44,27.44 arc(50.8,29.48) 42.9,35.36 arc(41.52,36.38) 39.84,36.75 39.15,36.75 arc(38.94,36.67) v3(38.84,36.48)
  BOTTOM w0.203: C116.2 147.32,22.1
UNNAMED_2_CAP_I102_N2: length 117
  TOP w0.203: v3(39.63,38.94) 39.63,38.87 U101.P13 ; C118.2 v3(142.91,58.04)
  L10_SIG w0.091: v3(39.63,38.94) arc(39.79,39.08) 40,39.13 40.42,39.13 arc(43.69,38.69) 46.72,37.38 arc(50.9,35.56) 55.41,34.92 111.63,34.92 arc(115.87,35.56) 119.71,37.45 arc(122.37,39.01) 125.23,40.16 arc(129.4,42.27) 132.63,45.64 arc(134.51,49.19) 135.54,53.06 arc(136.28,55.43) 137.69,57.47 arc(138.93,58.29) 140.39,58.55 142.38,58.55 arc(142.75,58.4) v3(142.91,58.04)
UNNAMED_2_CAP_I103_N2: length 115.5
  TOP w0.203: v3(38.84,37.28) U101.N11
  L5_SIG w0.091: 147.32,22.86 arc(147.19,22.68) 146.98,22.61 146.52,22.61 arc(145.82,22.49) 145.2,22.14 arc(144.38,21.36) 143.62,20.51 arc(142.63,19.72) 141.39,19.44 133.34,19.44 arc(131.14,19.64) 129.02,20.23 arc(124.36,22.29) 119.93,24.81 arc(115.19,26.96) 110.04,27.69 60.44,27.69 arc(50.91,29.71) 43.09,35.52 arc(41.62,36.62) 39.84,37 39.15,37 arc(38.94,37.08) v3(38.84,37.28)
  BOTTOM w0.203: C115.2 147.32,22.86
UNNAMED_2_CAP_I104_N2: length 117.1
  TOP w0.203: v3(39.64,39.68) U101.P14 ; C117.2 v3(142.91,59.31)
  L10_SIG w0.091: v3(142.91,59.31) arc(142.75,58.95) 142.39,58.8 140.4,58.8 arc(138.83,58.52) 137.5,57.65 arc(136.05,55.54) 135.29,53.1 arc(134.27,49.28) 132.42,45.78 arc(129.25,42.48) 125.16,40.4 arc(122.26,39.24) 119.56,37.66 arc(115.79,35.81) 111.63,35.17 55.41,35.17 arc(50.97,35.81) 46.85,37.59 arc(43.76,38.93) 40.42,39.39 40,39.39 arc(39.77,39.47) v3(39.64,39.68)
UNNAMED_2_CAP_I105_N2: length 113.1
  TOP w0.203: U101.P11 v3(39.62,37.35)
  L5_SIG w0.091: 147.32,27.18 arc(147.05,27.31) 146.77,27.37 arc(145.48,27.15) 144.49,26.29 144.08,25.67 arc(142.94,24.62) 141.44,24.24 133.67,24.24 arc(127.49,25.16) 121.8,27.75 arc(116.17,30.3) 110.04,31.18 58.08,31.18 arc(50.63,32.45) 44.12,36.27 arc(42.45,37.25) 40.55,37.59 40.19,37.59 arc(39.88,37.53) v3(39.62,37.35)
  BOTTOM w0.203: C120.2 147.32,27.18
UNNAMED_2_CAP_I106_N2: length 113
  TOP w0.203: U101.P12 v3(39.58,38.01)
  L5_SIG w0.091: v3(39.58,38.01) arc(39.87,37.89) 40.19,37.85 40.55,37.85 arc(42.54,37.49) 44.28,36.46 arc(50.72,32.69) 58.08,31.43 110.04,31.43 arc(116.24,30.55) 121.94,27.96 arc(127.56,25.4) 133.67,24.5 141.44,24.5 arc(142.82,24.85) 143.87,25.81 144.28,26.43 arc(145.37,27.38) 146.79,27.62 arc(147.11,27.69) 147.32,27.94
  BOTTOM w0.203: C119.2 147.32,27.94
UNNAMED_2_ICS25FL208K_I27_HOLDN: length 2.2
  BOTTOM w0.203: R119.2 44.33,60.05
UNNAMED_2_ICS25FL208K_I27_WPN: length 2.3
  BOTTOM w0.203: R120.2 U102.3
UNNAMED_3_CAP_I159_N1: length 11.3
  TOP w0.305: R202.1 11.07,42.09
  TOP w0.394: 11.07,42.09 C201.1 9.6,43.56 arc(6.36,45.72) 2.55,46.48 J201.1
UNNAMED_3_CAP_I180_N1: length 12.9
  TOP w0.394: J202.1 6.55,22.61 arc(9.56,23.85) C208.1 R209.1
UNNAMED_3_CAP_I206_N1: length 17.2
  BOTTOM w0.305: 16.82,15.89 16.69,15.74
  BOTTOM w0.394: 16.69,15.74 16.55,15.56 C222.1 15.89,14.81 arc(11.35,11.76) 5.98,10.68 arc(3.62,10.67) J204.1
UNNAMED_3_CAP_I230_N1: length 18.3
  BOTTOM w0.305: R216.1 16.79,52.2
  BOTTOM w0.394: 16.79,52.2 C215.1 arc(12.91,56.99) 7.95,58.42 J203.1
UNNAMED_3_CAP_I241_N2: length 2.7
  TOP w0.305: 13.46,38.39 13.39,38.33
  TOP w0.457: 13.39,38.33 C240.2
  TOP w0.508: T201.2 14.42,38.78 C241.2 13.75,38.4 13.74,38.39 13.46,38.39
UNNAMED_3_CAP_I245_N1: length 2.7
  TOP w0.508: T202.2 14.42,29.29 C242.2 13.64,28.91 13.54,28.81 C243.1
UNNAMED_3_CAP_I248_N1: length 2.6
  BOTTOM w0.356: C244.1 C245.2
  BOTTOM w0.394: T205.2 20.4,48.23 19.83,49.22 C245.2
UNNAMED_3_CAP_I252_N1: length 2.6
  BOTTOM w0.356: C246.1 17.64,19.42
  BOTTOM w0.508: T207.2 C247.2 17.65,19.42 17.64,19.42
UNNAMED_3_CAP_I256_N2: length 1.1
  TOP w0.203: 14.42,40.05 14.92,40.05 ; C248.2 13.95,40.05
  TOP w0.394: 13.95,40.05 14.42,40.05 ; 14.6,40.06 14.59,40.05
UNNAMED_3_CAP_I257_N2: length 1.1
  TOP w0.203: C249.2 13.95,30.56 ; 14.42,30.56 14.92,30.56
  TOP w0.394: 14.6,30.56 14.6,30.56 ; 13.95,30.56 14.42,30.56
UNNAMED_3_CAP_I258_N2: length 0.7
  BOTTOM w0.305: C251.2 19.19,18.72
  BOTTOM w0.394: 19.19,18.72 19.51,19.22
UNNAMED_3_CAP_I259_N2: length 0.7
  BOTTOM w0.305: C250.2 18.42,48.73
  BOTTOM w0.394: 18.42,48.73 18.73,48.23
UNNAMED_4_CAP_I166_N1: length 4.6
  BOTTOM w0.203: C405.1 95.2,50.42 96.02,50.42 ; 96.02,50.42 96.83,50.42 R404.2 97.46,49.79 98.01,49.79 98.48,49.32 T401.3 ; 96.02,50.42 R405.2
UNNAMED_4_CAP_I168_N1: length 6.4
  BOTTOM w0.394: J401.1 107.27,47.87 R401.2 C401.1
UNNAMED_4_CAP_I168_N2: length 1.6
  BOTTOM w0.394: C401.2 T401.4
UNNAMED_4_CAP_I177_N1: length 4.6
  BOTTOM w0.203: 96.02,50.77 96.85,50.77 R403.1 97.49,51.42 97.99,51.42 98.43,51.86 T401.1 ; 96.02,50.77 R405.1 ; 96.02,50.77 95.2,50.77 C403.1
UNNAMED_4_CAP_I184_N1: length 61.4
  BOTTOM w0.203: R417.2 R413.1 108.27,60.61 107.45,61.44 105.03,61.44 103.54,59.96 103.54,56.53 106.9,53.17 113,53.17 115.6,50.57 115.6,45.41 113.65,43.46 100.87,43.46 96.93,47.39 89.65,47.39 88.43,48.61 88.43,49.34 88.76,49.67 C409.1
UNNAMED_4_CAP_I192_N2: length 1.2
  BOTTOM w0.203: R439.1 91.56,53.74 C415.2
UNNAMED_4_CAP_I292_N2: length 2.5
  TOP w0.203: C411.2 105.78,63.08 105.78,62.09 105.98,61.89 J405.1
UNNAMED_4_CAP_I294_N2: length 2.5
  TOP w0.203: C410.2 105.42,63.08 105.42,62.09 105.22,61.89 J404.1
UNNAMED_4_CAP_I303_N2: length 1.7
  TOP w0.203: J407.1 79.19,64.18 C413.2
UNNAMED_4_CAP_I304_N2: length 1.7
  TOP w0.203: J406.1 78.17,64.18 C412.2
UNNAMED_4_CAP_I329_N1: length 3.2
  TOP w0.203: R449.2 97.36,57 R450.2 95.84,56.44 v2(95.84,55.87)
  BOTTOM w0.203: C420.1 v2(95.84,55.87)
UNNAMED_4_CAP_I330_N1: length 3.3
  TOP w0.203: R448.2 97.36,57.63 R450.1 95.84,58.19 v2(95.84,58.83)
  BOTTOM w0.203: C419.1 v2(95.84,58.83)
UNNAMED_4_CMOSNC7WV125K8X_I27_1: length 3.6
  TOP w0.203: 115.71,48.39 U402.5
  TOP w0.254: R454.1 115.33,47.67 115.71,48.06 115.71,48.39
UNNAMED_4_CMOSNC7WV125K8X_I279_: length 1.4
  TOP w0.254: R453.1 116.72,52.2 116.71,52.19 U402.2
UNNAMED_4_CNBNC3P_I148_CNTR: length 10.5
  TOP w0.203: v2(79.05,58.41) 79.02,58.41 79.02,59.51 78.81,59.71 75.16,59.71 74.33,58.88 74.33,56.7 74.48,56.55 J411.1
  BOTTOM w0.203: R438.2 v2(79.05,58.41)
UNNAMED_4_CNBNC3P_I248_CNTR: length 10.5
  TOP w0.203: J410.1 73.71,56.55 73.98,56.82 73.98,59.03 75.01,60.07 78.81,60.07 79.02,60.27 v2(79.02,61.37)
  BOTTOM w0.203: R437.2 v2(79.02,61.37)
UNNAMED_4_CNBNC3P_I306_CNTR: length 1.7
  TOP w0.203: R430.2 68.39,64.18 J409.1
UNNAMED_4_CNBNC3P_I308_CNTR: length 1.7
  TOP w0.203: R429.2 69.41,64.18 J408.1
UNNAMED_4_CNBNC3P_I318_CNTR: length 11.7
  TOP w0.203: J403.1 106.68,55.79 105.96,56.51 105.96,57.53 104.29,59.2 101.88,59.2 100.53,60.54 99.76,60.54 99.56,60.75 v2(99.56,61.88)
  BOTTOM w0.203: R422.1 v2(99.56,61.88)
UNNAMED_4_CNBNC3P_I321_CNTR: length 11.7
  TOP w0.203: J402.1 105.29,55.79 105.61,56.11 105.61,57.38 104.14,58.84 101.73,58.84 100.38,60.19 99.76,60.19 99.56,59.98 99.56,58.85 v2(99.52,58.85)
  BOTTOM w0.203: R421.1 v2(99.52,58.85)
UNNAMED_4_CNBNC3P_I324_CNTR: length 9.5
  TOP w0.203: J412.1 100.97,50.97 100.52,50.97 100.32,51.17 100.32,57.41 99.91,57.82 R448.1
UNNAMED_4_CNBNC3P_I325_CNTR: length 9.5
  TOP w0.203: J413.1 99.57,50.59 99.96,50.98 99.96,57.27 99.76,57.47 99.34,57.47 99.19,57.32 99.19,56.94 99.05,56.79 98.56,56.79 R449.1
UNNAMED_4_CNTP1P_I73_N1: length 11.5
  TOP w0.203: R444.2 99.71,67.72 TP403.1
  BOTTOM w0.203: TP403.1 101.31,66.12 U405.1
UNNAMED_4_CNTP1P_I74_N1: length 9.5
  TOP w0.203: TP402.1 101.98,66.21 98.3,66.21 97.79,66.71 R445.2
  BOTTOM w0.305: TP402.1 106.37,67.48 U405.3
UNNAMED_4_DIOLED_I333_P: length 1.5
  TOP w0.203: R446.2 DS401.A
UNNAMED_4_DIOLED_I334_P: length 1.5
  TOP w0.203: R447.2 DS402.A
UNNAMED_4_NC7WZ17P6X_I76_Y1: length 2.8
  TOP w0.203: R446.1 v2(109.74,67.22)
  BOTTOM w0.203: v2(109.74,67.22) 109.74,66.98 108.88,66.12 U405.6
UNNAMED_4_NC7WZ17P6X_I76_Y2: length 1.9
  TOP w0.203: R447.1 v2(109.1,68.37)
  BOTTOM w0.203: U405.4 109.1,68.19 v2(109.1,68.37)
UNNAMED_4_RES_I165_N2: length 61.4
  BOTTOM w0.203: R411.1 87.74,49.67 88.07,49.34 88.07,48.46 89.5,47.04 96.78,47.04 100.72,43.1 113.8,43.1 115.96,45.26 115.96,50.71 113.14,53.53 107.05,53.53 103.9,56.68 103.9,58.23 104.34,58.67 105.64,58.67 106.67,57.65 107.62,57.65 107.96,57.98 107.96,59.13 R412.2 R410.2
UNNAMED_4_RES_I268_N2: length 1.6
  BOTTOM w0.394: T401.5 R402.2
UNNAMED_5_CNTP1P_I268_N1: length 2
  BOTTOM w0.508: 22.61,64.05 TP604.1 23.62,63.03
UNNAMED_5_RES_I164_N2: length 3.3
  BOTTOM w0.762: R613.1 7.75,46.52 7.64,46.52 7.62,46.54 ; 6.99,47.66 R608.2
  BOTTOM w1.016: 6.99,47.66 7.24,47.41 7.62,47.41 ; 7.62,47.41 TP610.1 ; 7.62,47.41 7.62,46.54
UNNAMED_5_RES_I174_N2: length 5.8
  BOTTOM w0.394: R604.2 TP606.1 R612.1
UNNAMED_7_CAP_I11_N2: length 1.5
  TOP w0.203: C802.2 v1(139.12,55.52)
  BOTTOM w0.203: v1(139.12,55.52) 139.74,54.9 P801.D5
UNNAMED_7_CAP_I12_N2: length 1.5
  TOP w0.203: C801.2 140.39,55.5 v1(140.36,55.47)
  BOTTOM w0.203: P801.D4 139.74,56.1 v1(140.36,55.47)
UNNAMED_7_CAP_I157_N2: length 25.5
  TOP w0.203: C803.2 140.84,55.28 140.84,55.27 140.56,54.99 140.56,54.99 140.46,54.89 140.29,54.89 140.05,54.65 140.05,54.34 140.55,53.84 143.21,53.84 143.8,53.25 143.8,38.56 142.52,37.27 142.52,35.58 v1(142.91,35.18)
  BOTTOM w0.203: v1(142.91,35.18) P801.B20
UNNAMED_7_CAP_I158_N2: length 25.5
  TOP w0.203: v1(141.67,35.14) 142.16,35.63 142.16,37.42 143.45,38.71 143.45,53.11 143.07,53.49 140.4,53.49 139.67,54.22 139.67,54.27 139.59,54.35 139.59,54.43 139.3,54.71 139.23,54.71 C804.2
  BOTTOM w0.203: v1(141.67,35.14) 142.27,34.54 P801.B21
UNNAMED_7_CN400PAK_I2_N8: length 1.6
  TOP w0.203: v1(140.39,51.71) 140.27,51.6 R834.2
  BOTTOM w0.203: v1(140.39,51.71) 140.39,51.7 P801.D8
UNNAMED_7_CN400PAK_I2_N9: length 1.2
  TOP w0.203: v1(139.1,49.15) 139.13,49.18 R835.2
  BOTTOM w0.203: P801.D9 v1(139.1,49.15)
UNNAMED_7_CN400PAK_I2_N14: length 1.5
  TOP w0.305: R846.2 140.38,42.79 v1(140.37,42.8)
  BOTTOM w0.203: P801.D14 v1(140.37,42.8)
UNNAMED_7_CN400PAK_I2_N15: length 1.5
  TOP w0.305: v1(140.37,41.53) 140.38,41.52 R847.2
  BOTTOM w0.203: P801.D15 v1(140.37,41.53)
UNNAMED_7_CN400PAK_I2_N17: length 92.4
  L8_SIG w0.114: v1(139.1,40.26) 137.34,42.02 108.76,42.02 104.19,46.59 91.06,46.59 89.67,45.19 88.02,45.19 87.84,45.38 78.11,45.38 77.41,44.68 72.52,44.68 70.69,42.85 v2(52.61,42.85)
  BOTTOM w0.203: R838.2 v2(52.61,42.85) ; P801.D17 v1(139.1,40.26)
UNNAMED_7_CN400PAK_I2_N18: length 90.2
  L8_SIG w0.114: v1(139.1,38.99) 138.23,38.99 136.28,40.94 123.71,40.94 123.7,40.95 123.27,40.95 123.26,40.94 107.96,40.94 103.39,45.51 90.74,45.51 89.85,44.62 87.63,44.62 87.51,44.74 78.49,44.74 77.6,43.85 72.52,43.85 71,42.33 69.41,42.33 69.03,41.95 v2(63.18,41.95)
  BOTTOM w0.203: v2(63.18,41.95) 62.28,42.85 R839.2 ; P801.D18 v1(139.1,38.99)
UNNAMED_7_CN400PAK_I27_N10: length 1.2
  TOP w0.203: v1(140.37,47.88) 140.4,47.91 R816.2
  BOTTOM w0.203: P801.C10 v1(140.37,47.88)
UNNAMED_7_CN400PAK_I27_N11: length 1.2
  TOP w0.203: v1(141.64,47.88) 141.61,47.92 R817.2
  BOTTOM w0.203: P801.C11 v1(141.64,47.88)
UNNAMED_7_CN400PAK_I27_N18: length 97.4
  L8_SIG w0.114: v2(53.28,36.81) 58.61,36.81 60.07,38.27 60.07,39.28 60.84,40.04 62.8,40.04 63.63,40.87 70.42,40.87 72.77,43.22 80.27,43.22 80.91,43.86 90.25,43.86 90.81,44.43 101.93,44.43 106.91,39.45 135.49,39.45 135.76,39.18 135.76,39.11 136.4,38.47 136.84,38.47 137.59,37.72 v1(141.64,37.72)
  BOTTOM w0.203: v2(53.28,36.81) 52.5,36.81 R841.2 ; v1(141.64,37.72) P801.C18
UNNAMED_7_CN400PAK_I27_N19: length 95.3
  L8_SIG w0.114: v2(64.07,40.04) 76.52,40.04 77.41,40.93 77.41,41.82 78.36,42.78 84.97,42.78 85.45,43.26 90.53,43.26 91,43.73 100.08,43.73 105.66,38.15 125.49,38.15 126.25,37.38 127.57,37.38 128.06,37.86 130.09,37.86 130.93,37.02 141.07,37.02 v1(141.64,36.45)
  BOTTOM w0.203: v1(141.64,36.45) P801.C19 ; R842.2 55.23,38.11 55.23,39.32 55.96,40.04 v2(64.07,40.04)
UNNAMED_7_CN400PAK_I27_N22: length 1.3
  TOP w0.203: v1(141.64,32.64) 141.67,32.67 R843.2
  BOTTOM w0.394: v1(141.64,32.64) P801.C22
UNNAMED_7_CN400PAK_I27_N23: length 1.4
  TOP w0.203: R844.2 140.35,32.62 v1(140.37,32.64)
  BOTTOM w0.394: P801.C23 v1(140.37,32.64)
UNNAMED_7_CN400PAK_I52_N2: length 1.5
  TOP w0.305: R801.2 133.69,58.37 v1(134.02,58.04)
  BOTTOM w0.203: v1(134.02,58.04) P801.H2
UNNAMED_7_CN400PAK_I52_N7: length 6.3
  TOP w0.203: v1(134.02,52.97) 134.02,52.69 133.82,52.49 133.42,52.49 133.18,52.73 132,52.73 131.8,52.53 130.31,52.53 130.02,52.52 129.7,52.84 R802.2
  BOTTOM w0.203: v1(134.02,52.97) 134.02,52.96 P801.H7
UNNAMED_7_CN400PAK_I52_N8: length 6.3
  TOP w0.203: v1(134.02,51.65) 134.02,51.93 133.82,52.13 133.27,52.13 133.03,52.37 132.15,52.37 131.95,52.17 130.31,52.17 130.02,52.17 129.71,51.85 R803.2
  BOTTOM w0.203: P801.H8 134.06,51.65 v1(134.02,51.65)
UNNAMED_7_CN400PAK_I52_N10: length 1.8
  TOP w0.394: v1(135.29,47.88) 134.67,48.5 R804.2
  BOTTOM w0.203: P801.H10 v1(135.29,47.88)
UNNAMED_7_CN400PAK_I52_N11: length 1.8
  TOP w0.394: v1(135.29,46.61) 134.7,47.21 R805.2
  BOTTOM w0.203: v1(135.29,46.61) P801.H11
UNNAMED_7_CN400PAK_I52_N13: length 1.5
  TOP w0.394: R806.2 v1(134.02,44.07)
  BOTTOM w0.203: v1(134.02,44.07) P801.H13
UNNAMED_7_CN400PAK_I52_N14: length 1.5
  TOP w0.394: R807.2 v1(135.29,44.07)
  BOTTOM w0.203: P801.H14 v1(135.29,44.07)
UNNAMED_7_CN400PAK_I52_N16: length 1.7
  TOP w0.203: v1(134.02,41.53) 134.02,41.15 R836.2
  BOTTOM w0.203: P801.H16 v1(134.02,41.53)
UNNAMED_7_CN400PAK_I52_N17: length 95.2
  L5_SIG w0.114: v2(64.07,38.52) 68.39,38.52 74.49,44.62 75.88,44.62 78.43,47.16 87.82,47.16 87.98,47.01 98.78,47.01 102.87,51.09 104.4,51.09 106.3,53 116.4,53 117.29,52.11 124.65,52.11 127.12,49.64 129.36,49.64 130.44,48.56 132.77,48.56 134.83,46.51 134.83,46.42 135.1,46.15 135.19,46.15 137.16,44.17 137.16,41.51 137.03,41.37 137.03,41.34 136.76,41.07 136.72,41.07 136.53,40.87 134.62,40.87 134.02,40.27 v1(134.02,40.26)
  BOTTOM w0.203: v1(134.02,40.26) P801.H17
  BOTTOM w0.254: v2(64.07,38.52) 62.92,37.37 59.57,37.37
UNNAMED_7_CN400PAK_I52_N19: length 1.3
  TOP w0.203: R808.2 134,37.7 v1(134.02,37.72)
  BOTTOM w0.394: v1(134.02,37.72) P801.H19
UNNAMED_7_CN400PAK_I52_N20: length 1.3
  TOP w0.203: R809.2 134,36.43 v1(134.02,36.45)
  BOTTOM w0.394: v1(134.02,36.45) P801.H20
UNNAMED_7_CN400PAK_I52_N22: length 1.5
  TOP w0.203: R810.2 134.97,32.96 v1(135.29,32.64)
  BOTTOM w0.203: v1(135.29,32.64) P801.H22
UNNAMED_7_CN400PAK_I52_N23: length 1.5
  TOP w0.203: v1(135.29,31.37) 134.97,31.69 R811.2
  BOTTOM w0.203: v1(135.29,31.37) P801.H23
UNNAMED_7_CN400PAK_I52_N25: length 1.2
  TOP w0.203: v1(134.02,30.1) 134,30.08 R812.2
  BOTTOM w0.394: v1(134.02,30.1) P801.H25
UNNAMED_7_CN400PAK_I52_N26: length 61.9
  TOP w0.203: R813.2 89.92,44.36 91.64,46.08 95.38,46.08 v3(99.57,41.89)
  L7_SIG w0.114: v3(99.57,41.89) 99.57,41.86 102.13,39.29 129.17,39.29 129.48,39.6 135.34,39.6 135.83,39.11 135.83,31.25 135.49,30.91 135.26,30.91 134.56,30.2 134.56,29.76 134.02,29.22 v1(134.02,28.83)
  BOTTOM w0.394: v1(134.02,28.83) P801.H26
UNNAMED_7_CN400PAK_I52_N28: length 1.6
  TOP w0.203: R814.2 135,24.73 v1(135.29,25.02)
  BOTTOM w0.203: P801.H28 v1(135.29,25.02)
UNNAMED_7_CN400PAK_I52_N29: length 1.7
  TOP w0.203: v1(135.29,23.75) 135,23.46 R815.2
  BOTTOM w0.203: P801.H29 v1(135.29,23.75)
UNNAMED_7_CN400PAK_I55_N6: length 1.3
  TOP w0.203: R818.2 136.46,52.81 v1(136.59,52.94)
  BOTTOM w0.203: v1(136.59,52.94) 136.59,52.94 P801.G6
UNNAMED_7_CN400PAK_I55_N7: length 1.3
  TOP w0.203: v1(136.59,51.67) 136.46,51.79 R819.2
  BOTTOM w0.203: v1(136.59,51.67) 136.59,51.67 P801.G7
UNNAMED_7_CN400PAK_I55_N9: length 1.3
  TOP w0.203: v1(136.56,49.15) 136.59,49.13 R820.2
  BOTTOM w0.203: P801.G9 v1(136.56,49.15)
UNNAMED_7_CN400PAK_I55_N10: length 1.3
  TOP w0.203: v1(136.56,47.88) 136.59,47.86 R821.2
  BOTTOM w0.203: P801.G10 v1(136.56,47.88)
UNNAMED_7_CN400PAK_I55_N12: length 1.6
  TOP w0.203: v1(135.29,45.34) 135.43,45.48 R845.2
  BOTTOM w0.203: P801.G12 v1(135.29,45.34)
UNNAMED_7_CN400PAK_I55_N15: length 1.2
  TOP w0.203: R830.2 136.46,41.63 v1(136.56,41.53)
  BOTTOM w0.203: P801.G15 v1(136.56,41.53)
UNNAMED_7_CN400PAK_I55_N16: length 1.2
  TOP w0.203: v1(135.29,41.53) 135.32,41.56 R831.2
  BOTTOM w0.203: P801.G16 v1(135.29,41.53)
UNNAMED_7_CN400PAK_I55_N18: length 1.3
  TOP w0.203: v1(136.56,37.72) 136.31,37.98 R822.2
  BOTTOM w0.394: v1(136.56,37.72) P801.G18
UNNAMED_7_CN400PAK_I55_N19: length 1.3
  TOP w0.203: v1(135.29,37.72) 135.27,37.7 R823.2
  BOTTOM w0.394: P801.G19 v1(135.29,37.72)
UNNAMED_7_CN400PAK_I55_N21: length 1.2
  TOP w0.203: v1(135.29,33.91) 135.26,33.95 R824.2
  BOTTOM w0.203: P801.G21 v1(135.29,33.91)
UNNAMED_7_CN400PAK_I55_N22: length 1.2
  TOP w0.203: v1(136.56,33.91) 136.53,33.95 R825.2
  BOTTOM w0.203: P801.G22 v1(136.56,33.91)
UNNAMED_7_CN400PAK_I55_N24: length 1.6
  TOP w0.203: R826.2 136.12,30.92 v1(136.56,31.37)
  BOTTOM w0.203: P801.G24 v1(136.56,31.37)
UNNAMED_7_CN400PAK_I55_N25: length 1.9
  TOP w0.203: v1(136.56,28.83) 136.28,29.11 136.09,29.11 135.98,29.22 R827.2
  BOTTOM w0.394: v1(136.56,28.83) P801.G25
UNNAMED_7_CN400PAK_I55_N27: length 1.4
  TOP w0.203: v1(135.29,27.56) 134.92,27.19 R828.2
  BOTTOM w0.203: P801.G27 v1(135.29,27.56)
UNNAMED_7_CN400PAK_I55_N28: length 1.4
  TOP w0.203: R829.2 134.97,25.97 v1(135.29,26.29)
  BOTTOM w0.203: P801.G28 v1(135.29,26.29)
UNNAMED_7_CN400PAK_I67_N1: length 4.5
  TOP w0.394: v1(137.83,60.58) 136.56,60.58 135.12,62.02 R848.2
  BOTTOM w0.394: P801.F1 v1(137.83,60.58)
UNNAMED_9_AD7291_I112_DCAP: length 2.7
  TOP w0.305: 44.21,9.96 44.46,10.21 45.35,10.21 45.73,10.59 U703.8
  TOP w0.394: 44.21,9.96 C706.1
UNNAMED_9_AD7291_I112_VIN0: length 5.3
  TOP w0.305: R714.1 R715.1 53.48,8.81 52.09,10.21 51.58,10.21 51.2,10.59 U703.18
UNNAMED_9_AD7291_I112_VIN1: length 4.6
  TOP w0.305: R717.2 53.62,11.04 ; 53.62,11.04 R716.2 ; 53.62,11.04 53.58,11.09 U703.19
UNNAMED_9_AD7291_I112_VIN2: length 5.3
  TOP w0.305: R719.2 R718.2 53.48,13.39 52.09,11.99 51.19,11.99 50.79,11.59 U703.20
UNNAMED_9_AD7291_I112_VIN3: length 4.7
  TOP w0.305: R721.2 R720.2 51.56,15.22 49.52,13.18 U703.1
UNNAMED_9_AD7291_I112_VIN4: length 4
  TOP w0.254: U703.2 49.02,12.62 49.02,13.68 49.47,14.14 R722.2 R723.2
UNNAMED_9_AD7291_I112_VIN5: length 3.9
  TOP w0.305: U703.3 48.51,12.62 48.51,14.34 48.4,14.44 R725.2 R724.2
UNNAMED_9_AD7291_I112_VIN7: length 4.3
  TOP w0.305: U703.5 47.52,13.53 46.29,14.76 R727.2 R726.2
UNNAMED_9_AD7291_I112_VREF: length 2.3
  TOP w0.305: C705.1 45.01,11.22 45.6,11.22 45.74,11.09 U703.7
UNNAMED_9_CN20PV2_I59_N1: length 35.2
  TOP w0.203: v3(68.84,54.52) 68.07,55.28 65.03,55.28 61.85,58.46 60.71,58.46 60.2,58.97 P701.2 ; R702.1 v3(85.72,44.3)
  L10_SIG w0.114: v3(85.72,44.3) 80.72,44.3 77.73,47.29 72.51,47.29 70.87,48.93 70.87,52.36 68.84,54.4 v3(68.84,54.52)
UNNAMED_9_CN20PV2_I59_N2: length 33.7
  TOP w0.203: R704.1 60.64,35.28 61.22,35.85 61.22,36.68 60.2,37.7 v3(60.2,45.51)
  TOP w0.394: P701.4 v2(58.93,58.07)
  L10_SIG w0.114: v3(60.2,45.51) 60.2,45.51 59.06,46.65 59.05,46.65 57.66,48.05 57.66,52.75 54.61,55.8 54.61,57.89 55.82,59.09 57.9,59.09 v2(58.93,58.07)
UNNAMED_9_CN20PV2_I59_N3: length 45.7
  TOP w0.203: R705.1 88.82,45.02 v3(88.2,45.63)
  TOP w0.394: P701.6 v2(57.66,58.07)
  L10_SIG w0.114: v2(57.66,58.07) 57.27,58.46 56.14,58.46 55.76,58.08 55.76,57.06 56.9,55.92 61.47,55.92 62.23,55.16 69.09,55.16 71.5,52.74 71.5,49.57 73.15,47.92 79.01,47.92 81.3,45.63 v3(88.2,45.63)
UNNAMED_9_CN20PV2_I59_N4: length 51
  TOP w0.203: R706.1 87.51,36.76 v2(87.51,46.65)
  TOP w0.394: P701.8 v2(56.39,57.89)
  L10_SIG w0.114: v2(56.39,57.89) 56.77,57.51 57.66,57.51 58.52,56.65 59.58,56.65 62.03,59.09 65.79,59.09 68.26,56.62 73.98,56.62 76.58,54.01 78.88,54.01 79.89,53.01 79.89,51.92 81,50.81 81.62,50.81 82.27,50.16 82.27,49.54 85.16,46.65 v2(87.51,46.65)
UNNAMED_9_CN20PV2_I59_N8: length 61.3
  TOP w0.203: v2(85.99,51.86) 85.99,49.01 84.95,47.97 84.95,37.27 86.87,35.35 88.15,35.35 88.72,35.92 R707.1
  TOP w0.394: P701.16 v2(51.31,58.07)
  L10_SIG w0.114: v2(85.99,51.86) 84.46,53.39 82.29,53.39 78.49,57.19 75.44,57.19 71.76,60.87 70.36,60.87 70.23,60.75 53.99,60.75 v2(51.31,58.07)
UNNAMED_9_CN20PV2_I60_N6: length 4.1
  TOP w0.394: TP702.1 53.85,65.93 P701.11
